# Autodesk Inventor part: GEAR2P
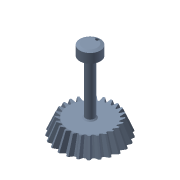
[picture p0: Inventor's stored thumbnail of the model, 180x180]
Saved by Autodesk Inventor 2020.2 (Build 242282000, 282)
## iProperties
+MSCProtocol1+ProtocolID: P00051221230020796
+MSCProtocol2+Protocol: P00051221230020796<@PID>[LOGS]<@EL>1=~-~-2147483640~~~<@EL>2=2005-12-22 00:01:37: ~Kontrola wytrzymałościowa jest OK.~-2147483640~~~txtcheck<@EL>[Synchronize]<@
Manager: www.cadconsulting.pl
Company: Fabian Stasiak CAD Consulting
Shininess: 20.0
Length Units: 11269
Angle Units: 11279
Time Units: 11290
Mass Units: 11283
Length Display Precision: 3
Angle Display Precision: 2
Created: 2001-01
Part Number: GEAR2P
Material: Stal, miękka
Document SubType Name: Modeling
Description: Przekładnie zębate stożkowe 25/66, 4
Density: 7.86 g/cm^3
Appearance: Stalowoniebieska - jasna
Designer: F.Stasiak
Density: 7.86
Volumn: 5.864026952018771
Area: 31.42094824814569
PropertySet Name: Model Information
Control State: 0
Master: False
Checked Out: False
TAB_mte: 4
TAB_z1: 25
TAB_z2: 66
TAB_betam: 20
TAB_x: 0.1632
TAB_xt: 0
TAB_delta1: 20.7461
TAB_delta2: 69.2539
TAB_IT: 6e26
TAB_fpt1: ±0.011
TAB_fpt2: ±0.012
TAB_tfa: 0
TAB_sk1: 5.682
TAB_sk2: 4.883
TAB_ECs1: -0.04
TAB_ECd1: -0.1
TAB_ECs2: -0.056
TAB_ECd2: -0.136
TAB_hk1: 3.619
TAB_hk2: 2.459
TAB_omega: 90
TAB_de1: 100
TAB_de2: 264
TAB_le: 141.152
TAB_deltaf1: 19.0632
TAB_deltaf2: 67.0417
TAB_alfat: 20
Subject: Zbiór ćwiczeń. Autodesk Inventor 2020. Kurs podstawowy
Author: F.Stasiak
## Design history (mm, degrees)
sketch "Base Body Sketch"
  geometry: L1 (42.799, 2.455)-(36.319, 0); L2 (42.799, 2.455)-(54.351, -25.25); L3 (54.351, -25.25)-(46.121, -28.367); L4 (-1.609, 0)-(20.914, 0) reference; L5 (36.319, 0)-(0, 0); L6 (0, -28.367)-(46.121, -28.367); L7 (0, 0)-(0, -28.367); L8 (42.799, 2.455)-(0, 105.102); L9 (0, 0)-(0, 105.102); L10 (0, -22.98)-(0, 29.259) reference; L11 (0, 105.102)-(50, -26.898); L12 (0, 105.102)-(36.319, 0); L13 (36.319, 0)-(46.121, -28.367)
  constraints: 22 end point, 3 collinear, 2 parallel, 2 perpendicular, 2 point on line
  dimensions: "d33" = 30 distance between parallel lines of L3 L1 (= prf_b); "d34" = 108.702 diameter of L2.end L7 (= msp_dae); "d35" = 92.243 diameter of L3.end L7 (= msp_dfe); "d37" = 141.152 distance from line of L3 L8.end (= prf_le); "d41" = 20.7461 deg angle of L9 L11 (= msp_delta); "d59" = 36.31898 distance of L5.end L1.end (derived)
revolve "Base Body" sketch "Base Body Sketch" stored, may be unused: angle "d10" = 360 deg
node "Tooth Plane"
workpoint "Work Point"
sketch "Sketch2"
  geometry: L1 (6.151, 6.413)-(-6.151, 6.413); L2 (0, -7.667)-(6.151, 6.413); L3 (-6.151, 6.413)-(0, -7.667); L4 (0, 2.5)-(0, -3) reference; L5 (0, 2.5)-(0, -3) reference; L6 (0, 2.5)-(0, -3) reference; L7 (0, -30.954)-(0, 16.239) reference; L8 (0, -30.954)-(0, 16.239) reference; L9 (19.305, -37.23)-(-25.74, -37.23) reference; A1 r 8.384 centre (0, 0.717) between (-6.151, 6.413) and (0, -7.667); 1 further point; 1 other entity
  constraints: 6 end point, 3 point on circle, 2 point on line, 1 centre point, 1 horizontal, 1 vertical alignment, 1 other
  dimensions: "d42" = 47.2 deg angle of L3 L2 (= msp_a2); "d43" = 14.08 distance from line of L2.start L1 (= 1.6 x msp_he); "d54" = 38.50684 distance of L2.start point (0, -46.174) (= msp_y)
extrude "Tooth" cut sketch "Sketch2" distance "d18" = 30.6 (= 1.02 x prf_b); taper "d19" = -1.41691 deg (= msp_a1)
revolve "Fix Body" stored, may be unused: angle "d23" = 360 deg
sketch "Sketch7"
  geometry: L1 (-12, 0)-(16, 0) reference; L2 (0, -12)-(0, 16) reference; 2 further points
  constraints: 1 coincident
hole "Hole" sketch "Sketch7" diameter "d47" = 23.06075 (= hole); stored, may be unused: countersink angle "d51" = 60 deg, drill point angle "d53" = 118 deg; dims "d48" = 6, "d49" = 4, "d50" = 2, "d52" = 8
node "Gear Axis"
node "Intersection"
node "Mesh Plane"
sketch "Szkic8"
  geometry: C1 r 7.5 at (0, 0); A1 r 36.319 centre (0, 0) between (10.099, 34.887) and (7.957, 35.437) reference
  constraints: 1 centre point, 1 coincident
  dimensions: "d67" = 15 diameter of C1
extrude "Wyciągnięcie proste2" join sketch "Szkic8" distance "d68" = 110; taper "d69" = 0 deg
sketch "Szkic9"
  geometry: C1 r 7.5 at (0, 0) reference; C2 r 17.5 at (0, 0)
  constraints: 1 centre point, 1 coincident
  dimensions: "d70" = 35 diameter of C2
extrude "Wyciągnięcie proste3" join sketch "Szkic9" distance "d71" = 20; taper "d72" = 0 deg
chamfer "Faza1" distance "d73" = 2; stored, may be unused: second distance "d74" = 5, angle "d75" = 45 deg
chamfer "Faza2" distance "d76" = 2; stored, may be unused: second distance "d77" = 5, angle "d78" = 45 deg
chamfer "Faza3" distance "d79" = 2; stored, may be unused: second distance "d80" = 5, angle "d81" = 45 deg
sketch "Szkic10"
  geometry: C1 r 3 at (-0.088, 12.5); 1 further point
  constraints: 1 centre point, 2 other
  dimensions: "d82" = 6 diameter of C1
extrude "Wyciągnięcie proste4" cut sketch "Szkic10" stored distance "d83" = 20; taper "d84" = 0 deg
node "Bryła1"
node "Korpusy bryłowe"
node "Korpusy powierzchniowe"
pattern_circular "Tooth Pattern" dims angle "d22" = 360 deg
sketch "Sketch3"
  geometry: L1 (-36.319, 0)-(0, 0); L2 (-46.121, -28.367)-(-36.319, 0); L3 (0, -28.367)-(-46.121, -28.367); L4 (0, 0)-(0, -28.367); L5 (-46.121, -28.367)-(46.121, -28.367) reference; L6 (-36.319, 0)-(36.319, 0) reference; L7 (0, -21.174)-(0, 5.775) reference; 1 further point
  constraints: 8 end point, 2 horizontal, 2 point on line, 1 vertical
  dimensions: "d57" = 92.243 diameter of L2.start L7 (= msp_dfe); "d58" = 0 distance between parallel lines of L7 L4; "d60" = 36.31898 distance of L1.start L1.end (= d59)
other parameters: "prf_le" = 141.152 [user parameter; used in 3 equation terms], "prf_delta1" = 3.62088 [user parameter; used in 1 equation term], "prf_he1" = 8.8 [user parameter; used in 1 equation term], "prf_dfe1" = 92.243 [user parameter; used in 1 equation term], "prf_dae1" = 108.702 [user parameter; used in 1 equation term], "prf_b" = 30 [user parameter; used in 2 equation terms], "prf_omega" = 90 deg [user parameter; used in 1 equation term], "msp_delta" = 20.7461 deg (= prf_delta1) [user parameter; used in 3 equation terms], "msp_he" = 8.8 (= prf_he1) [user parameter; used in 2 equation terms], "msp_dfe" = 92.243 (= prf_dfe1) [user parameter; used in 3 equation terms], "msp_dae" = 108.702 (= prf_dae1) [user parameter; used in 2 equation terms], "hole" = 23.06075 (= 0.25 x msp_dfe) [user parameter; used in 1 equation term], "msp_y" = 38.50684 (computed from msp_delta, msp_dae, msp_he) [user parameter; used in 1 equation term], "msp_a1" = -1.41691 deg (computed from msp_de, msp_z, prf_le) [user parameter; used in 1 equation term], "msp_a2" = 47.2 deg (computed from msp_z) [user parameter; used in 1 equation term], "msp_dist" = 131.99961 (computed from prf_le, msp_delta) [user parameter], "d0" = 3.62545 (derived), "d4" = 38.7702 (derived), "d6" = 32.175 (derived), "d8" = 21.89 (derived), "d12" = 0 (derived), "d14" = -13.24579 (derived), "d16" = 9.83731 (derived), "d40" = 19.14 (derived), "d62" = 0, "d63" = 90 deg (= prf_omega), "d64" = 3.78788 (computed from prf_z1, prf_z2), "d65" = 0, "d66" = 0
